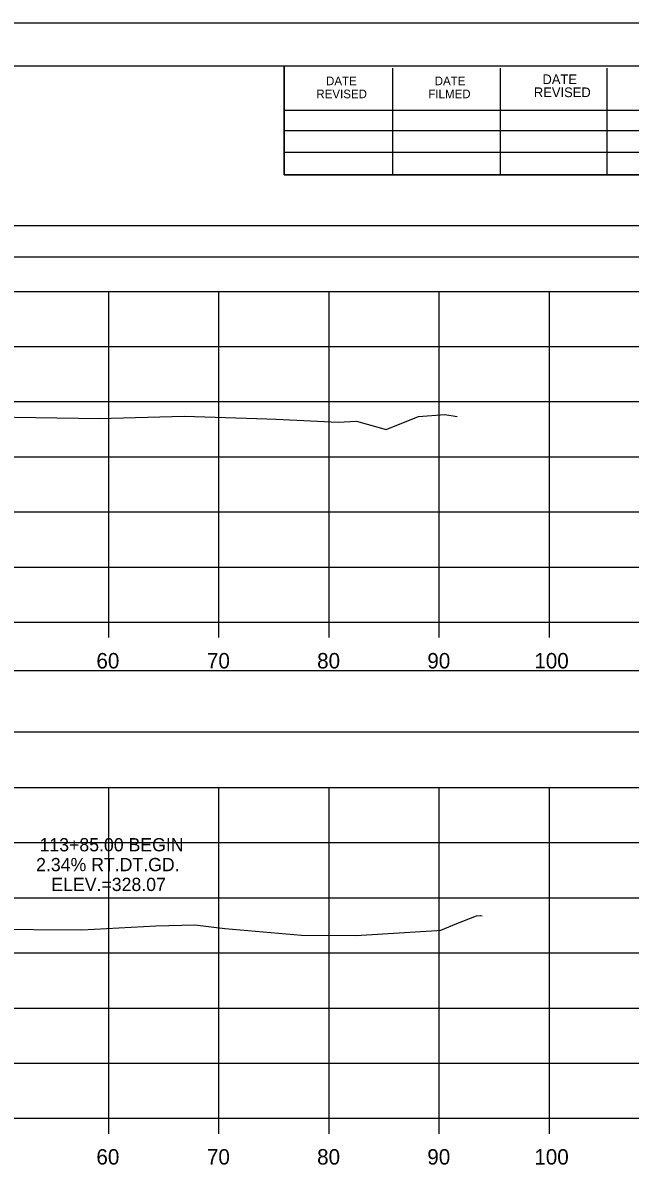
# Model space of a CAD drawing. Extents: x 1376273 to 1384221, y 378927 to 384592.
# Drawn here: x 1377110 to 1377165.1, y 379794.8 to 379898.5 of the extents above; entities that cross this region are included whole.
import ezdxf

# ---------------------------------------------------------------- set-up
doc = ezdxf.new("R2010")
doc.units = 0
for name, color, linetype in [('R_Axis', 7, 'Continuous'), ('R_Axis Annot', 7, 'Continuous'), ('R_Border', 7, 'Continuous'), ('R_Exist Surface', 7, 'Continuous'), ('R_Grid', 7, 'Continuous'), ('R_No Plot', 7, 'Continuous'), ('R_Xsect Elev', 7, 'Continuous')]:
    doc.layers.add(name, color=color, linetype=linetype)

msp = doc.modelspace()

# ---------------------------------------------------------------- linework, layer by layer
at = {"layer": 'R_Axis'}
for p, q in [((1376907.77, 379844.14), (1377207.77, 379844.14)), ((1377117.77, 379842.74), (1377117.77, 379844.14)), ((1377127.77, 379842.74), (1377127.77, 379844.14)), ((1377137.77, 379842.74), (1377137.77, 379844.14)), ((1377147.77, 379842.74), (1377147.77, 379844.14)), ((1377157.77, 379842.74), (1377157.77, 379844.14)), ((1376907.77, 379799.14), (1377207.77, 379799.14)), ((1377117.77, 379797.74), (1377117.77, 379799.14)), ((1377127.77, 379797.74), (1377127.77, 379799.14)), ((1377137.77, 379797.74), (1377137.77, 379799.14)), ((1377147.77, 379797.74), (1377147.77, 379799.14)), ((1377157.77, 379797.74), (1377157.77, 379799.14))]:
    msp.add_line(p, q, dxfattribs=at)
at = {"layer": 'R_Axis Annot'}
for points in [[(1376907.2, 379877.28), (1377209.01, 379877.28), (1377209.01, 379880.1), (1376907.2, 379880.1)], [(1376907.2, 379834.2), (1377209.01, 379834.2), (1377209.01, 379839.72), (1376907.2, 379839.72)]]:
    msp.add_lwpolyline(points, close=True, dxfattribs=at)
at = {"layer": 'R_Border'}
for p, q in [((1376899.77, 379894.6), (1377215.95, 379894.6)), ((1377133.69, 379884.72), (1377133.69, 379894.6)), ((1377143.55, 379884.72), (1377143.55, 379894.4)), ((1377153.31, 379884.72), (1377153.31, 379894.4)), ((1377162.99, 379884.72), (1377162.99, 379894.4)), ((1377133.69, 379890.58), (1377172.85, 379890.58)), ((1377133.69, 379888.72), (1377172.85, 379888.72)), ((1377133.69, 379884.72), (1377133.69, 379886.78)), ((1377133.69, 379886.78), (1377172.85, 379886.78)), ((1377215.95, 379884.72), (1377133.69, 379884.72))]:
    msp.add_line(p, q, dxfattribs=at)
at = {"layer": 'R_Exist Surface'}
for points in [[(1377101.54, 379862.86), (1377116.9, 379862.6), (1377124.6, 379862.82), (1377132.11, 379862.57), (1377132.96, 379862.56), (1377138.6, 379862.27), (1377140.26, 379862.37), (1377142.95, 379861.62), (1377145.88, 379862.79), (1377148.28, 379862.96), (1377149.38, 379862.79)], [(1377102.27, 379816.32), (1377115.34, 379816.24), (1377122.03, 379816.58), (1377125.59, 379816.68), (1377128.32, 379816.34), (1377135.26, 379815.75), (1377140.2, 379815.71), (1377147.53, 379816.17), (1377147.92, 379816.2), (1377149.35, 379816.79), (1377151.14, 379817.5), (1377151.5, 379817.53), (1377151.67, 379817.5)]]:
    msp.add_lwpolyline(points, dxfattribs=at)
at = {"layer": 'R_Grid'}
for p, q in [((1376907.77, 379874.14), (1377207.77, 379874.14)), ((1376907.77, 379874.14), (1377207.77, 379874.14)), ((1377117.77, 379844.14), (1377117.77, 379874.14)), ((1377117.77, 379844.14), (1377117.77, 379874.14)), ((1377127.77, 379844.14), (1377127.77, 379874.14)), ((1377127.77, 379844.14), (1377127.77, 379874.14)), ((1377137.77, 379844.14), (1377137.77, 379874.14)), ((1377137.77, 379844.14), (1377137.77, 379874.14)), ((1377147.77, 379844.14), (1377147.77, 379874.14)), ((1377147.77, 379844.14), (1377147.77, 379874.14)), ((1377157.77, 379844.14), (1377157.77, 379874.14)), ((1377157.77, 379844.14), (1377157.77, 379874.14)), ((1376907.77, 379869.14), (1377207.77, 379869.14)), ((1376907.77, 379869.14), (1377207.77, 379869.14)), ((1376907.77, 379864.14), (1377207.77, 379864.14)), ((1376907.77, 379864.14), (1377207.77, 379864.14)), ((1376907.77, 379859.14), (1377207.77, 379859.14)), ((1376907.77, 379859.14), (1377207.77, 379859.14)), ((1376907.77, 379854.14), (1377207.77, 379854.14)), ((1376907.77, 379854.14), (1377207.77, 379854.14)), ((1376907.77, 379849.14), (1377207.77, 379849.14)), ((1376907.77, 379849.14), (1377207.77, 379849.14)), ((1376907.77, 379844.14), (1377207.77, 379844.14)), ((1376907.77, 379844.14), (1377207.77, 379844.14)), ((1376907.77, 379829.14), (1377207.77, 379829.14)), ((1376907.77, 379829.14), (1377207.77, 379829.14)), ((1377117.77, 379799.14), (1377117.77, 379829.14)), ((1377117.77, 379799.14), (1377117.77, 379829.14)), ((1377127.77, 379799.14), (1377127.77, 379829.14)), ((1377127.77, 379799.14), (1377127.77, 379829.14)), ((1377137.77, 379799.14), (1377137.77, 379829.14)), ((1377137.77, 379799.14), (1377137.77, 379829.14)), ((1377147.77, 379799.14), (1377147.77, 379829.14)), ((1377147.77, 379799.14), (1377147.77, 379829.14)), ((1377157.77, 379799.14), (1377157.77, 379829.14)), ((1377157.77, 379799.14), (1377157.77, 379829.14)), ((1376907.77, 379824.14), (1377207.77, 379824.14)), ((1376907.77, 379824.14), (1377207.77, 379824.14)), ((1376907.77, 379819.14), (1377207.77, 379819.14)), ((1376907.77, 379819.14), (1377207.77, 379819.14)), ((1376907.77, 379814.14), (1377207.77, 379814.14)), ((1376907.77, 379814.14), (1377207.77, 379814.14)), ((1376907.77, 379809.14), (1377207.77, 379809.14)), ((1376907.77, 379809.14), (1377207.77, 379809.14)), ((1376907.77, 379804.14), (1377207.77, 379804.14)), ((1376907.77, 379804.14), (1377207.77, 379804.14)), ((1376907.77, 379799.14), (1377207.77, 379799.14)), ((1376907.77, 379799.14), (1377207.77, 379799.14))]:
    msp.add_line(p, q, dxfattribs=at)
at = {"layer": 'R_No Plot'}
msp.add_line((1376887.37, 379898.5), (1377220.7, 379898.5), dxfattribs=at)
for points in [[(1376887.36, 379898.5), (1377220.7, 379898.5), (1377220.7, 379685.16), (1376887.36, 379685.16)], [(1377133.69, 379894.6), (1377133.69, 379884.72), (1377169.42, 379884.72), (1377169.42, 379881.8), (1377192.62, 379881.8), (1377192.62, 379857.47), (1377215.95, 379857.47), (1377215.95, 379689.14), (1376899.77, 379689.14), (1376899.77, 379894.6)]]:
    msp.add_lwpolyline(points, close=True, dxfattribs=at)

# ---------------------------------------------------------------- texts
at = {"layer": 'R_Axis Annot'}
for s, p in [('60', (1377116.65, 379839.94)), ('70', (1377126.68, 379839.94)), ('80', (1377136.68, 379839.94)), ('90', (1377146.68, 379839.94)), ('100', (1377156.39, 379839.94)), ('60', (1377116.65, 379794.94)), ('70', (1377126.68, 379794.94)), ('80', (1377136.68, 379794.94)), ('90', (1377146.68, 379794.94)), ('100', (1377156.39, 379794.94))]:
    msp.add_text(s, height=1.4, dxfattribs=at).set_placement(p)
at = {"layer": 'R_Border'}
for s, height, p in [('DATE', 0.782, (1377137.49, 379892.84)), ('DATE', 0.782, (1377147.35, 379892.84)), ('DATE', 0.879, (1377157.13, 379892.94)), ('REVISED', 0.782, (1377136.61, 379891.66)), ('FILMED', 0.782, (1377146.77, 379891.66)), ('REVISED', 0.879, (1377156.35, 379891.76))]:
    msp.add_text(s, height=height, rotation=360, dxfattribs=at).set_placement(p)
at = {"layer": 'R_Xsect Elev'}
for s, p in [('113+85.00 BEGIN', (1377111.49, 379823.35)), ('2.34% RT.DT.GD.', (1377111.18, 379821.55)), ('ELEV.=328.07', (1377112.56, 379819.75))]:
    msp.add_text(s, height=1.2, rotation=360, dxfattribs=at).set_placement(p)

doc.saveas('drawing.dxf')
